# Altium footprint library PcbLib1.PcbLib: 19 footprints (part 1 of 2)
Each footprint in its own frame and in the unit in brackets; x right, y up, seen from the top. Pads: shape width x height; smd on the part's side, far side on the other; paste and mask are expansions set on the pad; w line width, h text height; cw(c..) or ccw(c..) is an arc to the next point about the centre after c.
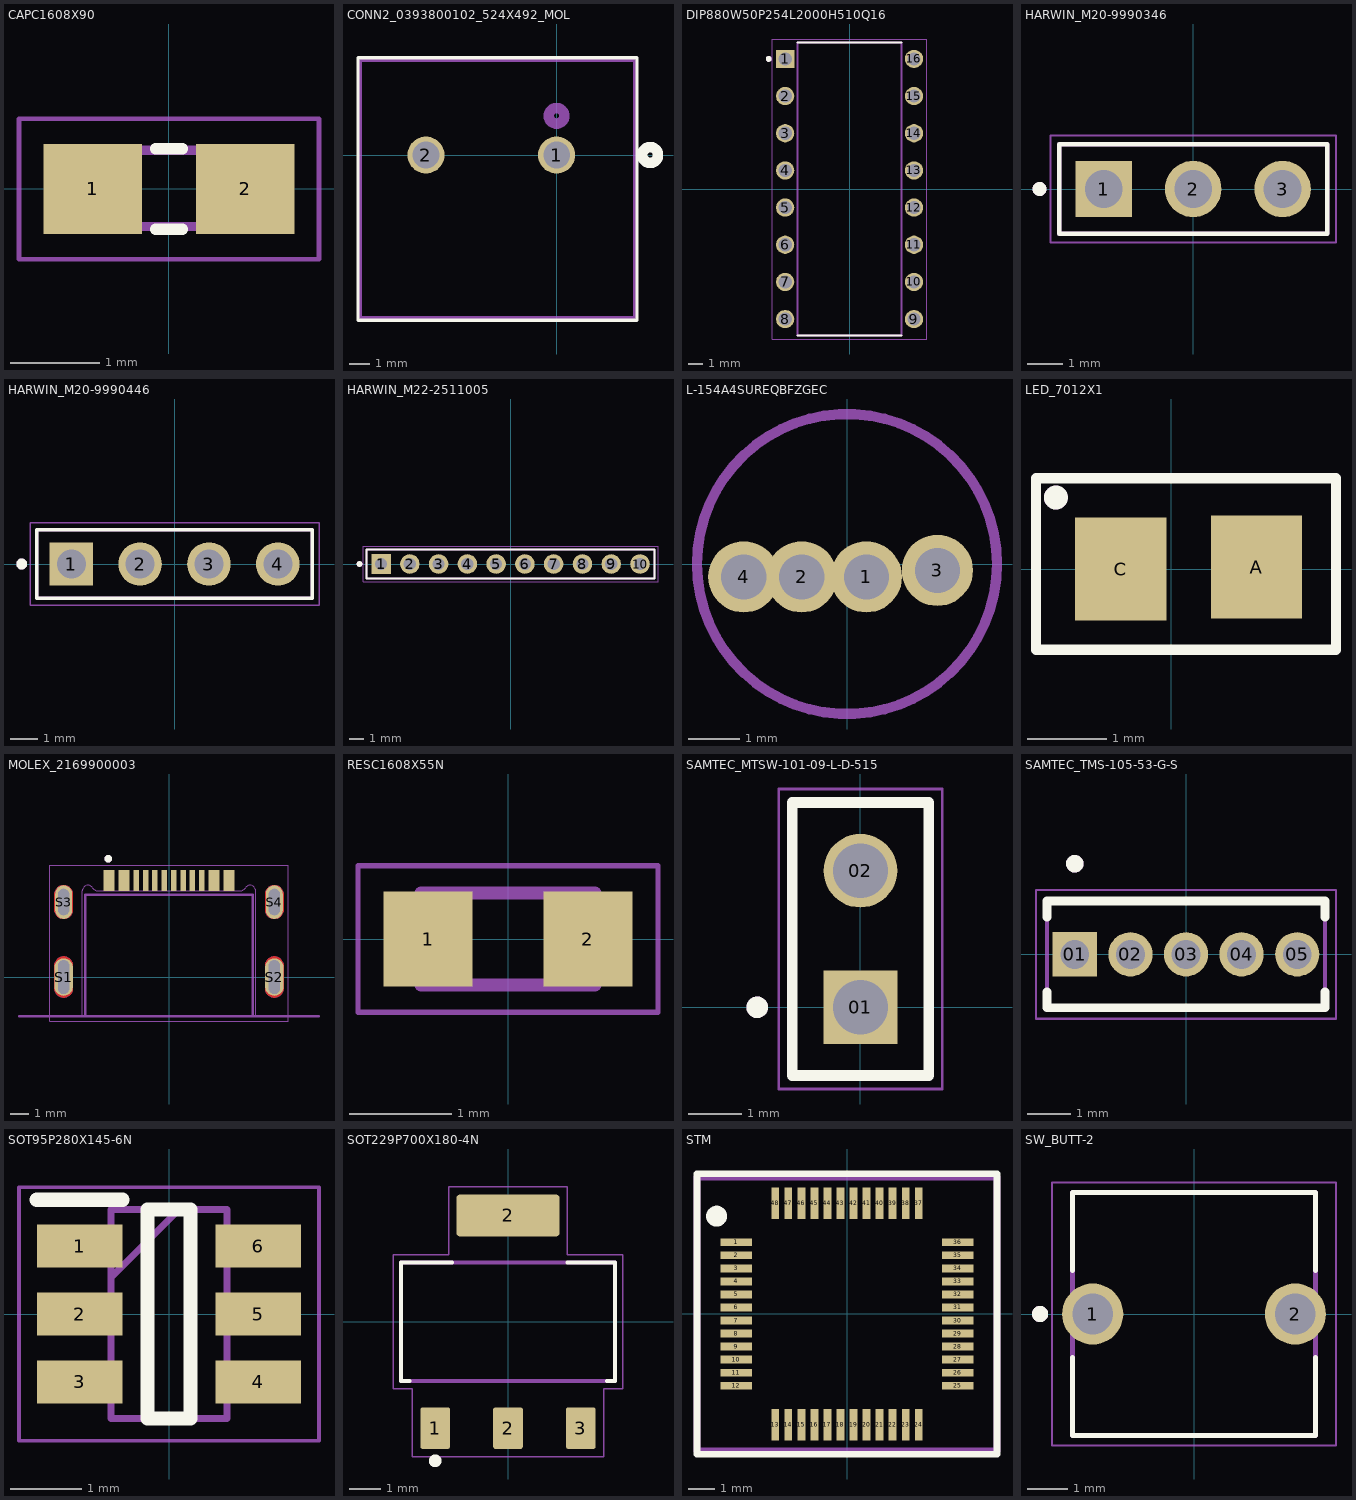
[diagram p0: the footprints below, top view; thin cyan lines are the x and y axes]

## CAPC1608X90 [mm]
pads (2):
  rect 1.1x1 smd: 1(-0.85,0) 2(0.85,0)
Top Overlay:
  lines w0.127: -0.15,-0.45 0.15,-0.45 ; -0.15,0.45 0.15,0.45
Mechanical 13:
  region: -0.338,-0.47 -0.839,-0.47 -0.839,0.48 -0.338,0.48
  region: 0.83,-0.471 0.331,-0.471 0.331,0.48 0.83,0.48
  lines w0.102: -0.356,-0.419 0.356,-0.419 ; -0.356,0.432 0.356,0.432
Mechanical 15:
  lines w0.051: -1.673,-0.783 1.673,-0.783 1.673,0.783 -1.673,0.783 -1.673,-0.783
3D body "C0603X102K5RAC3316.STEP": height 0.87, standoff 0, extent -0.8,-0.4 0.8,0.4

## CONN2_0393800102_524X492_MOL [mil]
pads (2):
  round 71 hole 51: 1(0,0) 2(-250,0)
Top Overlay:
  lines w6: -380,-316 -380,186 154,186 154,-316 -380,-316
  lines w20: 164,0 cw(c179,0) 194,0 cw(c179,0) 164,0
Bottom Overlay:
  lines w20: 164,0 cw(c179,0) 194,0 cw(c179,0) 164,0
Mechanical 13:
  lines w6: -375,-311 -375,181 149,181 149,-311 -375,-311
  lines w20: -15,75 cw(c0,75) 15,75 cw(c0,75) -15,75
3D body "393800102.stp": height 311, standoff -181, extent -370,-312 154,751

## DIP880W50P254L2000H510Q16 [mm]
height 5.1
pads (16):
  rect 1.25x1.25 / inner round 1.25 / far side rect 1.25x1.25 hole 0.9: 1(-4.4,8.89)
  round 1.25 hole 0.9: 2(-4.4,6.35) 3(-4.4,3.81) 4(-4.4,1.27) 5(-4.4,-1.27) 6(-4.4,-3.81) 7(-4.4,-6.35) 8(-4.4,-8.89) 9(4.4,-8.89) 10(4.4,-6.35) 11(4.4,-3.81) 12(4.4,-1.27) 13(4.4,1.27) 14(4.4,3.81) 15(4.4,6.35) 16(4.4,8.89)
Top Overlay:
  circle w0.2: c-5.525,8.89 r0.1
  lines w0.127: -3.55,-10 3.55,-10 ; -3.55,10 3.55,10
Mechanical 13:
  circle w0.2: c-5.525,8.89 r0.1
  lines w0.127: -3.55,-10 3.55,-10 3.55,10 -3.55,10 -3.55,-10
Mechanical 15:
  lines w0.05: -5.275,-10.25 5.275,-10.25 5.275,10.25 -5.275,10.25 -5.275,-10.25
3D body "step_temp.STEP": height 5.1, standoff -3.3, extent -4.62,-9.746 4.62,10.254

## HARWIN_M20-9990346 [mm]
pads (3):
  rect 1.605x1.605 / inner round 1.605 / far side rect 1.605x1.605 hole 1.07: 1(-2.54,0)
  round 1.605 hole 1.07: 2(0,0) 3(2.54,0)
Top Overlay:
  circle w0.2: c-4.37,0 r0.1
  lines w0.127: -3.81,-1.27 -3.81,1.27 3.81,1.27 3.81,-1.27 -3.81,-1.27
Mechanical 13:
  circle w0.2: c-4.37,0 r0.1
  lines w0.127: -3.81,-1.27 -3.81,1.27 3.81,1.27 3.81,-1.27 -3.81,-1.27
Mechanical 15:
  lines w0.05: -4.06,-1.52 -4.06,1.52 4.06,1.52 4.06,-1.52 -4.06,-1.52
3D body "step_temp.STEP": height 8.74, standoff -3, extent -3.81,-1.27 3.81,1.27

## HARWIN_M20-9990446 [mm]
pads (4):
  rect 1.605x1.605 / inner round 1.605 / far side rect 1.605x1.605 hole 1.07: 1(-3.81,0)
  round 1.605 hole 1.07: 2(-1.27,0) 3(1.27,0) 4(3.81,0)
Top Overlay:
  circle w0.2: c-5.64,0 r0.1
  lines w0.127: -5.08,-1.27 5.08,-1.27 5.08,1.27 -5.08,1.27 -5.08,-1.27
Mechanical 13:
  circle w0.2: c-5.64,0 r0.1
  lines w0.127: -5.08,-1.27 5.08,-1.27 5.08,1.27 -5.08,1.27 -5.08,-1.27
Mechanical 15:
  lines w0.05: -5.33,-1.52 5.33,-1.52 5.33,1.52 -5.33,1.52 -5.33,-1.52
3D body "step_temp.STEP": height 8.74, standoff -3, extent -5.08,-1.27 5.08,1.27

## HARWIN_M22-2511005 [mm]
pads (10):
  rect 1.358x1.358 / inner round 1.358 / far side rect 1.358x1.358 hole 0.85: 1(-9,0)
  round 1.358 hole 0.85: 2(-7,0) 3(-5,0) 4(-3,0) 5(-1,0) 6(1,0) 7(3,0) 8(5,0) 9(7,0) 10(9,0)
Top Overlay:
  circle w0.2: c-10.5,0 r0.1
  lines w0.127: -10,-1 10,-1 10,1 -10,1 -10,-1
Mechanical 13:
  circle w0.2: c-10.5,0 r0.1
  lines w0.127: -10,-1 10,-1 10,1 -10,1 -10,-1
Mechanical 15:
  lines w0.05: -10.25,-1.25 10.25,-1.25 10.25,1.25 -10.25,1.25 -10.25,-1.25
3D body "m22-2511005.stp": height 3.5, standoff -3.8, extent -10,-1 10,1

## L-154A4SUREQBFZGEC [mil]
pads (4):
  round 55.12 hole 35: 1(15,-10) 2(-35,-10) 3(70,-5) 4(-80,-10)
Mechanical 13:
  circle w7.87: c0,0 r116.14
3D body "step_temp.STEP": height 377.95, standoff -1043.31, extent -108.43,-120.9 106.14,110.9

## LED_7012X1 [mm]
height 1
pads (2):
  rect 1.15x1.3 smd: A(1.075,0.025) C(-0.635,0)
Top Overlay:
  circle w0.2: c-1.45,0.9 r0.05
  lines w0.127: -1.7,-1.016 2.075,-1.016 2.075,1.143 -1.7,1.143 -1.7,-1.016
Mechanical 13:
  lines w0.2: -1.4,0.9 cw(c-1.45,0.9) -1.4,0.902
3D body "step_temp.STEP": height 0.73, standoff 0, extent -0.737,-0.622 1.27,0.622

## MOLEX_2169900003 [mm]
height 2.31
pads (16):
  rect 0.6x1.1 smd: A1_B12(-3.2,5.15) A4_B9(-2.4,5.15) B1_A12(3.2,5.15) B4_A9(2.4,5.15)
  rect 0.3x1.1 smd: A5(-1.25,5.15) A6(-0.25,5.15) A7(0.25,5.15) A8(1.25,5.15) B5(1.75,5.15) B6(0.75,5.15) B7(-0.75,5.15) B8(-1.75,5.15)
  oval 1x2 hole 0.6 slot 1.8 at 90 deg mask+0: S1(-5.62,0) S2(5.62,0)
  oval 0.9x1.8 hole 0.6 slot 1.4 at 90 deg mask+0: S3(-5.62,4) S4(5.62,4)
Top Layer:
  region: 5.672,1.097 5.724,1.089 5.775,1.076 5.823,1.057 5.87,1.033 5.914,1.005 5.955,0.972 5.992,0.935 6.025,0.894 6.053,0.85 6.077,0.803 6.096,0.755 6.109,0.704 6.117,0.652 6.12,0.6 6.12,-0.6 6.117,-0.652 6.109,-0.704 6.096,-0.755 6.077,-0.803 6.053,-0.85 6.025,-0.894 5.992,-0.935 5.955,-0.972 5.914,-1.005 5.87,-1.033 5.823,-1.057 5.775,-1.076 5.724,-1.089 5.672,-1.097 5.62,-1.1 5.568,-1.097 5.516,-1.089 5.465,-1.076 5.417,-1.057 5.37,-1.033 5.326,-1.005 5.285,-0.972 5.248,-0.935 5.215,-0.894 5.187,-0.85 5.163,-0.803 5.144,-0.755 5.131,-0.704 5.123,-0.652 5.12,-0.6 5.12,0.6 5.123,0.652 5.131,0.704 5.144,0.755 5.163,0.803 5.187,0.85 5.215,0.894 5.248,0.935 5.285,0.972 5.326,1.005 5.37,1.033 5.417,1.057 5.465,1.076 5.516,1.089 5.568,1.097 5.62,1.1
  region: 5.672,4.897 5.724,4.889 5.775,4.876 5.823,4.857 5.87,4.833 5.914,4.805 5.955,4.772 5.992,4.735 6.025,4.694 6.053,4.65 6.077,4.603 6.096,4.555 6.109,4.504 6.117,4.452 6.12,4.4 6.12,3.6 6.117,3.548 6.109,3.496 6.096,3.445 6.077,3.397 6.053,3.35 6.025,3.306 5.992,3.265 5.955,3.228 5.914,3.195 5.87,3.167 5.823,3.143 5.775,3.124 5.724,3.111 5.672,3.103 5.62,3.1 5.568,3.103 5.516,3.111 5.465,3.124 5.417,3.143 5.37,3.167 5.326,3.195 5.285,3.228 5.248,3.265 5.215,3.306 5.187,3.35 5.163,3.397 5.144,3.445 5.131,3.496 5.123,3.548 5.12,3.6 5.12,4.4 5.123,4.452 5.131,4.504 5.144,4.555 5.163,4.603 5.187,4.65 5.215,4.694 5.248,4.735 5.285,4.772 5.326,4.805 5.37,4.833 5.417,4.857 5.465,4.876 5.516,4.889 5.568,4.897 5.62,4.9
  region: -5.568,1.097 -5.516,1.089 -5.465,1.076 -5.417,1.057 -5.37,1.033 -5.326,1.005 -5.285,0.972 -5.248,0.935 -5.215,0.894 -5.187,0.85 -5.163,0.803 -5.144,0.755 -5.131,0.704 -5.123,0.652 -5.12,0.6 -5.12,-0.6 -5.123,-0.652 -5.131,-0.704 -5.144,-0.755 -5.163,-0.803 -5.187,-0.85 -5.215,-0.894 -5.248,-0.935 -5.285,-0.972 -5.326,-1.005 -5.37,-1.033 -5.417,-1.057 -5.465,-1.076 -5.516,-1.089 -5.568,-1.097 -5.62,-1.1 -5.672,-1.097 -5.724,-1.089 -5.775,-1.076 -5.823,-1.057 -5.87,-1.033 -5.914,-1.005 -5.955,-0.972 -5.992,-0.935 -6.025,-0.894 -6.053,-0.85 -6.077,-0.803 -6.096,-0.755 -6.109,-0.704 -6.117,-0.652 -6.12,-0.6 -6.12,0.6 -6.117,0.652 -6.109,0.704 -6.096,0.755 -6.077,0.803 -6.053,0.85 -6.025,0.894 -5.992,0.935 -5.955,0.972 -5.914,1.005 -5.87,1.033 -5.823,1.057 -5.775,1.076 -5.724,1.089 -5.672,1.097 -5.62,1.1
  region: -5.568,4.897 -5.516,4.889 -5.465,4.876 -5.417,4.857 -5.37,4.833 -5.326,4.805 -5.285,4.772 -5.248,4.735 -5.215,4.694 -5.187,4.65 -5.163,4.603 -5.144,4.555 -5.131,4.504 -5.123,4.452 -5.12,4.4 -5.12,3.6 -5.123,3.548 -5.131,3.496 -5.144,3.445 -5.163,3.397 -5.187,3.35 -5.215,3.306 -5.248,3.265 -5.285,3.228 -5.326,3.195 -5.37,3.167 -5.417,3.143 -5.465,3.124 -5.516,3.111 -5.568,3.103 -5.62,3.1 -5.672,3.103 -5.724,3.111 -5.775,3.124 -5.823,3.143 -5.87,3.167 -5.914,3.195 -5.955,3.228 -5.992,3.265 -6.025,3.306 -6.053,3.35 -6.077,3.397 -6.096,3.445 -6.109,3.496 -6.117,3.548 -6.12,3.6 -6.12,4.4 -6.117,4.452 -6.109,4.504 -6.096,4.555 -6.077,4.603 -6.053,4.65 -6.025,4.694 -5.992,4.735 -5.955,4.772 -5.914,4.805 -5.87,4.833 -5.823,4.857 -5.775,4.876 -5.724,4.889 -5.672,4.897 -5.62,4.9
Bottom Layer:
  region: 5.672,1.097 5.724,1.089 5.775,1.076 5.823,1.057 5.87,1.033 5.914,1.005 5.955,0.972 5.992,0.935 6.025,0.894 6.053,0.85 6.077,0.803 6.096,0.755 6.109,0.704 6.117,0.652 6.12,0.6 6.12,-0.6 6.117,-0.652 6.109,-0.704 6.096,-0.755 6.077,-0.803 6.053,-0.85 6.025,-0.894 5.992,-0.935 5.955,-0.972 5.914,-1.005 5.87,-1.033 5.823,-1.057 5.775,-1.076 5.724,-1.089 5.672,-1.097 5.62,-1.1 5.568,-1.097 5.516,-1.089 5.465,-1.076 5.417,-1.057 5.37,-1.033 5.326,-1.005 5.285,-0.972 5.248,-0.935 5.215,-0.894 5.187,-0.85 5.163,-0.803 5.144,-0.755 5.131,-0.704 5.123,-0.652 5.12,-0.6 5.12,0.6 5.123,0.652 5.131,0.704 5.144,0.755 5.163,0.803 5.187,0.85 5.215,0.894 5.248,0.935 5.285,0.972 5.326,1.005 5.37,1.033 5.417,1.057 5.465,1.076 5.516,1.089 5.568,1.097 5.62,1.1
  region: 5.672,4.897 5.724,4.889 5.775,4.876 5.823,4.857 5.87,4.833 5.914,4.805 5.955,4.772 5.992,4.735 6.025,4.694 6.053,4.65 6.077,4.603 6.096,4.555 6.109,4.504 6.117,4.452 6.12,4.4 6.12,3.6 6.117,3.548 6.109,3.496 6.096,3.445 6.077,3.397 6.053,3.35 6.025,3.306 5.992,3.265 5.955,3.228 5.914,3.195 5.87,3.167 5.823,3.143 5.775,3.124 5.724,3.111 5.672,3.103 5.62,3.1 5.568,3.103 5.516,3.111 5.465,3.124 5.417,3.143 5.37,3.167 5.326,3.195 5.285,3.228 5.248,3.265 5.215,3.306 5.187,3.35 5.163,3.397 5.144,3.445 5.131,3.496 5.123,3.548 5.12,3.6 5.12,4.4 5.123,4.452 5.131,4.504 5.144,4.555 5.163,4.603 5.187,4.65 5.215,4.694 5.248,4.735 5.285,4.772 5.326,4.805 5.37,4.833 5.417,4.857 5.465,4.876 5.516,4.889 5.568,4.897 5.62,4.9
  region: -5.568,4.897 -5.516,4.889 -5.465,4.876 -5.417,4.857 -5.37,4.833 -5.326,4.805 -5.285,4.772 -5.248,4.735 -5.215,4.694 -5.187,4.65 -5.163,4.603 -5.144,4.555 -5.131,4.504 -5.123,4.452 -5.12,4.4 -5.12,3.6 -5.123,3.548 -5.131,3.496 -5.144,3.445 -5.163,3.397 -5.187,3.35 -5.215,3.306 -5.248,3.265 -5.285,3.228 -5.326,3.195 -5.37,3.167 -5.417,3.143 -5.465,3.124 -5.516,3.111 -5.568,3.103 -5.62,3.1 -5.672,3.103 -5.724,3.111 -5.775,3.124 -5.823,3.143 -5.87,3.167 -5.914,3.195 -5.955,3.228 -5.992,3.265 -6.025,3.306 -6.053,3.35 -6.077,3.397 -6.096,3.445 -6.109,3.496 -6.117,3.548 -6.12,3.6 -6.12,4.4 -6.117,4.452 -6.109,4.504 -6.096,4.555 -6.077,4.603 -6.053,4.65 -6.025,4.694 -5.992,4.735 -5.955,4.772 -5.914,4.805 -5.87,4.833 -5.823,4.857 -5.775,4.876 -5.724,4.889 -5.672,4.897 -5.62,4.9
  region: -5.568,1.097 -5.516,1.089 -5.465,1.076 -5.417,1.057 -5.37,1.033 -5.326,1.005 -5.285,0.972 -5.248,0.935 -5.215,0.894 -5.187,0.85 -5.163,0.803 -5.144,0.755 -5.131,0.704 -5.123,0.652 -5.12,0.6 -5.12,-0.6 -5.123,-0.652 -5.131,-0.704 -5.144,-0.755 -5.163,-0.803 -5.187,-0.85 -5.215,-0.894 -5.248,-0.935 -5.285,-0.972 -5.326,-1.005 -5.37,-1.033 -5.417,-1.057 -5.465,-1.076 -5.516,-1.089 -5.568,-1.097 -5.62,-1.1 -5.672,-1.097 -5.724,-1.089 -5.775,-1.076 -5.823,-1.057 -5.87,-1.033 -5.914,-1.005 -5.955,-0.972 -5.992,-0.935 -6.025,-0.894 -6.053,-0.85 -6.077,-0.803 -6.096,-0.755 -6.109,-0.704 -6.117,-0.652 -6.12,-0.6 -6.12,0.6 -6.117,0.652 -6.109,0.704 -6.096,0.755 -6.077,0.803 -6.053,0.85 -6.025,0.894 -5.992,0.935 -5.955,0.972 -5.914,1.005 -5.87,1.033 -5.823,1.057 -5.775,1.076 -5.724,1.089 -5.672,1.097 -5.62,1.1
Top Overlay:
  circle w0.2: c-3.24,6.31 r0.1
Top Solder:
  drawing of 4 lines, arcs and shapes, not listed
Bottom Solder:
  drawing of 4 lines, arcs and shapes, not listed
Mechanical 1:
  lines w0: -4.62,-2.1 -4.62,4.6 cw(c-4.32,4.6) -4.06,4.75 ccw(c-3.8,4.9) -3.8,4.6 3.8,4.6 ccw(c3.8,4.9) 4.06,4.75 cw(c4.32,4.6) 4.62,4.6 4.62,-2.1 -4.62,-2.1
Mechanical 13:
  circle w0.2: c-3.24,6.31 r0.1
  lines w0.127: -8,-2.1 -4.47,-2.1 ; 8,-2.1 4.47,-2.1 ; -4.47,-2.1 -4.47,4.4 4.47,4.4 4.47,-2.1 ; -4.47,-2.1 4.47,-2.1
  text "PCB EDGE" at 6.64,-1.9 h0.41
Mechanical 15:
  lines w0.05: -6.37,-2.35 6.37,-2.35 6.37,5.95 -6.37,5.95 -6.37,-2.35
3D body "2169900003.stp": height 2.14, standoff -1.04, extent -5.673,-2.006 5.867,5.194

## RESC1608X55N [mm]
pads (2):
  rect 0.87x0.93 smd paste+0 mask+0.102: 1(-0.78,0) 2(0.78,0)
Mechanical 13:
  lines w0.127: -0.85,-0.45 -0.85,0.45 0.85,0.45 0.85,-0.45 -0.85,-0.45
Mechanical 15:
  lines w0.05: -1.465,-0.715 -1.465,0.715 1.465,0.715 1.465,-0.715 -1.465,-0.715
3D body "step_temp.STEP": height 0.55, standoff 0, extent -0.8,-0.4 0.8,0.4

## SAMTEC_MTSW-101-09-L-D-515 [mm]
pads (2):
  rect 1.37x1.37 hole 1.02: 01(0,0)
  round 1.37 hole 1.02: 02(0,2.54)
Top Overlay:
  circle w0.2: c-1.92,0 r0.1
  lines w0.2: -1.27,-1.27 1.27,-1.27 1.27,3.81 -1.27,3.81 -1.27,-1.27
Mechanical 13:
  circle w0.2: c-1.92,0 r0.1
  lines w0.1: -1.27,-1.27 1.27,-1.27 1.27,3.81 -1.27,3.81 -1.27,-1.27
Mechanical 15:
  lines w0.05: -1.52,-1.52 1.52,-1.52 1.52,4.06 -1.52,4.06 -1.52,-1.52
3D body "MTSW-101-09-L-D-515.stp": height 15.62, standoff -2.92, extent -1.27,-1.397 1.27,3.683

## SAMTEC_TMS-105-53-G-S [mm]
pads (5):
  rect 1.01x1.01 hole 0.66: 01(-2.54,0)
  round 1.01 hole 0.66: 02(-1.27,0) 03(0,0) 04(1.27,0) 05(2.54,0)
Top Overlay:
  circle w0.2: c-2.54,2.069 r0.1
  lines w0.2: -3.175,-0.855 -3.175,-1.219 3.175,-1.219 3.175,-0.855 ; -3.175,0.855 -3.175,1.219 3.175,1.219 3.175,0.855
Mechanical 13:
  circle w0.2: c-2.54,2.069 r0.1
  lines w0.1: -3.175,-1.219 -3.175,1.219 3.175,1.219 3.175,-1.219 -3.175,-1.219
Mechanical 15:
  lines w0.05: -3.425,-1.469 3.425,-1.469 3.425,1.469 -3.425,1.469 -3.425,-1.469
3D body "TMS-105-53-G-S.stp": height 9.78, standoff -3.05, extent -3.175,-1.168 3.175,1.27

## SOT95P280X145-6N [mm]
pads (6):
  rect 1.2x0.6 smd: 1(-1.25,0.95) 2(-1.25,0) 3(-1.25,-0.95) 4(1.25,-0.95) 5(1.25,0) 6(1.25,0.95)
Top Overlay:
  lines w0.2: -1.85,1.6 -0.65,1.6 ; -0.3,-1.462 0.3,-1.462 0.3,1.462 -0.3,1.462 -0.3,-1.462
Mechanical 13:
  lines w0.05: -2.1,-1.775 2.1,-1.775 2.1,1.775 -2.1,1.775 -2.1,-1.775
  lines w0.1: -0.812,0.512 0.138,1.462 ; -0.812,-1.462 0.812,-1.462 0.812,1.462 -0.812,1.462 -0.812,-1.462
3D body "step_temp.STEP": height 1.42, standoff -0.03, extent -1.4,-1.462 1.4,1.462

## SOT229P700X180-4N [mm]
pads (4):
  rrect15% 0.93x1.31 smd: 1(-2.29,-3.345) 2(0,-3.345) 3(2.29,-3.345)
  rrect15% 3.24x1.31 smd: 2(0,3.345)
Top Overlay:
  circle w0.2: c-2.29,-4.373 r0.1
  lines w0.127: -3.1,-1.86 -3.36,-1.86 -3.36,1.86 -1.76,1.86 ; 1.87,1.86 3.36,1.86 3.36,-1.86 3.11,-1.86
Mechanical 13:
  lines w0.127: -3.36,-1.86 -3.36,1.86 3.36,1.86 3.36,-1.86 -3.36,-1.86
Mechanical 15:
  lines w0.05: -3.61,-2.11 -3.61,2.11 -1.87,2.11 -1.87,4.25 1.87,4.25 1.87,2.11 3.61,2.11 3.61,-2.11 3.01,-2.11 3.01,-4.25 -3.01,-4.25 -3.01,-2.11 -3.61,-2.11
3D body "step_temp.STEP": height 1.8, standoff 0, extent -3.15,-3.5 3.15,3.5

## STM [mm]
pads (48):
  rect 1.2x0.3 smd mask+0.102: 1(-4.25,2.75) 2(-4.25,2.25) 3(-4.25,1.75) 4(-4.25,1.25) 5(-4.25,0.75) 6(-4.25,0.25) 7(-4.25,-0.25) 8(-4.25,-0.75) 9(-4.25,-1.25) 10(-4.25,-1.75) 11(-4.25,-2.25) 12(-4.25,-2.75) 25(4.25,-2.75) 26(4.25,-2.25) 27(4.25,-1.75) 28(4.25,-1.25) 29(4.25,-0.75) 30(4.25,-0.25) 31(4.25,0.25) 32(4.25,0.75) 33(4.25,1.25) 34(4.25,1.75) 35(4.25,2.25) 36(4.25,2.75)
  rect 0.3x1.2 smd mask+0.102: 13(-2.75,-4.25) 14(-2.25,-4.25) 15(-1.75,-4.25) 16(-1.25,-4.25) 17(-0.75,-4.25) 18(-0.25,-4.25) 19(0.25,-4.25) 20(0.75,-4.25) 21(1.25,-4.25) 22(1.75,-4.25) 23(2.25,-4.25) 24(2.75,-4.25) 37(2.75,4.25) 38(2.25,4.25) 39(1.75,4.25) 40(1.25,4.25) 41(0.75,4.25) 42(0.25,4.25) 43(-0.25,4.25) 44(-0.75,4.25) 45(-1.25,4.25) 46(-1.75,4.25) 47(-2.25,4.25) 48(-2.75,4.25)
Top Overlay:
  circle w0.4: c-5,3.75 r0.2
  lines w0.254: -5.75,-5.375 5.75,-5.375 5.75,5.375 -5.75,5.375 -5.75,-5.375
Mechanical 29:
  lines w0.254: -5.75,-5.25 -5.75,5.25 5.75,5.25 5.75,-5.25 -5.75,-5.25
  text ".Designator" at -2.996,-0.238 h1.52
3D body "STM32F103C8T6--3DModel-STEP-510211.STEP": height 1.6, standoff 0, extent -4.5,-4.5 4.5,4.5

## SW_BUTT-2 [mm]
height 9.5
pads (2):
  round 1.508 hole 1 mask+0.102: 1(-2.5,0) 2(2.5,0)
Top Overlay:
  circle w0.2: c-3.8,0 r0.1
  lines w0.127: -3,-1.075 -3,-3 3,-3 3,-1.075 ; -3,1.075 -3,3 3,3 3,1.075
Mechanical 13:
  circle w0.2: c-3.8,0 r0.1
  lines w0.127: -3,-3 3,-3 3,3 -3,3 -3,-3
Mechanical 15:
  lines w0.05: -3.504,-3.25 -3.504,3.25 3.504,3.25 3.504,-3.25 -3.504,-3.25
3D body "step_temp.STEP": height 5.1, standoff -4, extent -3,-3 3,3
